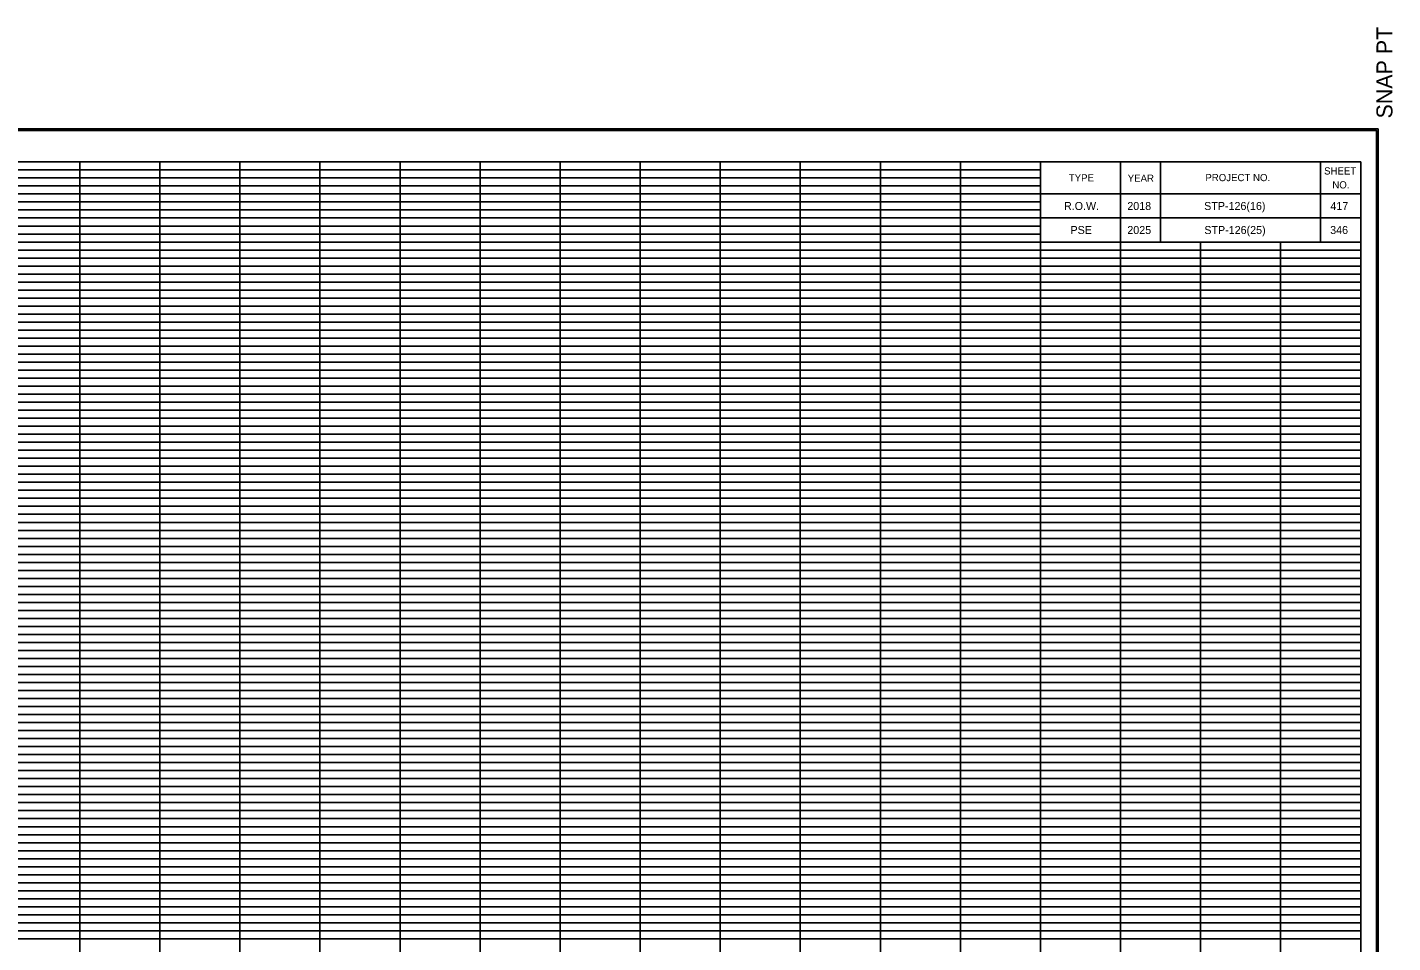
# Model space of a CAD drawing. Extents: x 980 to 2228, y 978 to 2394.
# Drawn here: x 1153.4 to 1324, y 1652.5 to 1766.8 of the extents above; entities that cross this region are included whole.
import ezdxf

# ---------------------------------------------------------------- set-up
doc = ezdxf.new("R2010")
doc.units = 0
for name, color, linetype in [('DESIGN - SCRATCH - User 1', 7, 'Continuous'), ('DESIGN - SHEET - Corner Text', 7, 'Continuous'), ('DESIGN - SHEET - Light Grid', 7, 'Continuous'), ('DESIGN - SHEET - Linework', 7, 'Continuous'), ('DESIGN - SHEET - Plot Shape', 7, 'Continuous'), ('DESIGN - TYPICAL - Finished Grade and Subgrade', 7, 'Continuous')]:
    doc.layers.add(name, color=color, linetype=linetype)

# ---------------------------------------------------------------- blocks, each defined once
blk = doc.blocks.new('XSTSHT')
at = {"layer": 'DESIGN - SCRATCH - User 1'}
for p, q in [((28.5, 20.45), (28.5, 20.45)), ((29.24, 20.45), (29.24, 20.45)), ((30.49, 20.45), (30.49, 20.45)), ((31.74, 20.45), (31.74, 20.45)), ((28.5, 20.15), (28.5, 20.15)), ((29.24, 20.15), (29.24, 20.15)), ((30.49, 20.15), (30.49, 20.15)), ((31.74, 20.15), (31.74, 20.15))]:
    blk.add_line(p, q, dxfattribs=at)
at = {"layer": 'DESIGN - SHEET - Light Grid'}
for p, q in [((8, 20.9), (16, 20.9)), ((16, 20.9), (24, 20.9)), ((24, 20.9), (28, 20.9)), ((8, 20.8), (16, 20.8)), ((8, 20.7), (16, 20.7)), ((16, 20.8), (24, 20.8)), ((16, 20.7), (24, 20.7)), ((24, 20.8), (28, 20.8)), ((24, 20.7), (28, 20.7)), ((8, 20.6), (16, 20.6)), ((8, 20.5), (16, 20.5)), ((16, 20.6), (24, 20.6)), ((16, 20.5), (24, 20.5)), ((24, 20.6), (28, 20.6)), ((24, 20.5), (28, 20.5)), ((8, 20.4), (16, 20.4)), ((8, 20.3), (16, 20.3)), ((16, 20.4), (24, 20.4)), ((16, 20.3), (24, 20.3)), ((24, 20.4), (28, 20.4)), ((24, 20.3), (28, 20.3)), ((8, 20.2), (16, 20.2)), ((16, 20.2), (24, 20.2)), ((24, 20.2), (28, 20.2)), ((8, 20.1), (16, 20.1)), ((16, 20.1), (24, 20.1)), ((24, 20.1), (28, 20.1)), ((8, 19.9), (16, 19.9)), ((8, 19.8), (16, 19.8)), ((16, 19.9), (24, 19.9)), ((16, 19.8), (24, 19.8)), ((24, 19.9), (32, 19.9)), ((24, 19.8), (32, 19.8)), ((8, 19.7), (16, 19.7)), ((16, 19.7), (24, 19.7)), ((24, 19.7), (32, 19.7)), ((8, 19.6), (16, 19.6)), ((8, 19.5), (16, 19.5)), ((16, 19.6), (24, 19.6)), ((16, 19.5), (24, 19.5)), ((24, 19.6), (32, 19.6)), ((24, 19.5), (32, 19.5)), ((8, 19.4), (16, 19.4)), ((8, 19.3), (16, 19.3)), ((16, 19.4), (24, 19.4)), ((16, 19.3), (24, 19.3)), ((24, 19.4), (32, 19.4)), ((24, 19.3), (32, 19.3)), ((8, 19.2), (16, 19.2)), ((16, 19.2), (24, 19.2)), ((24, 19.2), (32, 19.2)), ((8, 19.1), (16, 19.1)), ((16, 19.1), (24, 19.1)), ((24, 19.1), (32, 19.1)), ((8, 18.9), (16, 18.9)), ((8, 18.8), (16, 18.8)), ((16, 18.9), (24, 18.9)), ((16, 18.8), (24, 18.8)), ((24, 18.9), (32, 18.9)), ((24, 18.8), (32, 18.8)), ((8, 18.7), (16, 18.7)), ((8, 18.6), (16, 18.6)), ((16, 18.7), (24, 18.7)), ((16, 18.6), (24, 18.6)), ((24, 18.7), (32, 18.7)), ((24, 18.6), (32, 18.6)), ((8, 18.5), (16, 18.5)), ((16, 18.5), (24, 18.5)), ((24, 18.5), (32, 18.5)), ((8, 18.4), (16, 18.4)), ((8, 18.3), (16, 18.3)), ((16, 18.4), (24, 18.4)), ((16, 18.3), (24, 18.3)), ((24, 18.4), (32, 18.4)), ((24, 18.3), (32, 18.3)), ((8, 18.2), (16, 18.2)), ((8, 18.1), (16, 18.1)), ((16, 18.2), (24, 18.2)), ((16, 18.1), (24, 18.1)), ((24, 18.2), (32, 18.2)), ((24, 18.1), (32, 18.1)), ((8, 17.9), (16, 17.9)), ((8, 17.8), (16, 17.8)), ((16, 17.9), (24, 17.9)), ((16, 17.8), (24, 17.8)), ((24, 17.9), (32, 17.9)), ((24, 17.8), (32, 17.8)), ((8, 17.7), (16, 17.7)), ((8, 17.6), (16, 17.6)), ((16, 17.7), (24, 17.7)), ((16, 17.6), (24, 17.6)), ((24, 17.7), (32, 17.7)), ((24, 17.6), (32, 17.6)), ((8, 17.5), (16, 17.5)), ((8, 17.4), (16, 17.4)), ((16, 17.5), (24, 17.5)), ((16, 17.4), (24, 17.4)), ((24, 17.5), (32, 17.5)), ((24, 17.4), (32, 17.4)), ((8, 17.3), (16, 17.3)), ((16, 17.3), (24, 17.3)), ((24, 17.3), (32, 17.3)), ((8, 17.2), (16, 17.2)), ((8, 17.1), (16, 17.1)), ((16, 17.2), (24, 17.2)), ((16, 17.1), (24, 17.1)), ((24, 17.2), (32, 17.2)), ((24, 17.1), (32, 17.1)), ((8, 16.9), (16, 16.9)), ((16, 16.9), (24, 16.9)), ((24, 16.9), (32, 16.9)), ((8, 16.8), (16, 16.8)), ((16, 16.8), (24, 16.8)), ((24, 16.8), (32, 16.8)), ((8, 16.7), (16, 16.7)), ((8, 16.6), (16, 16.6)), ((16, 16.7), (24, 16.7)), ((16, 16.6), (24, 16.6)), ((24, 16.7), (32, 16.7)), ((24, 16.6), (32, 16.6)), ((8, 16.5), (16, 16.5)), ((8, 16.4), (16, 16.4)), ((16, 16.5), (24, 16.5)), ((16, 16.4), (24, 16.4)), ((24, 16.5), (32, 16.5)), ((24, 16.4), (32, 16.4)), ((8, 16.3), (16, 16.3)), ((16, 16.3), (24, 16.3)), ((24, 16.3), (32, 16.3)), ((8, 16.2), (16, 16.2)), ((8, 16.1), (16, 16.1)), ((16, 16.2), (24, 16.2)), ((16, 16.1), (24, 16.1)), ((24, 16.2), (32, 16.2)), ((24, 16.1), (32, 16.1)), ((8, 15.9), (16, 15.9)), ((16, 15.9), (24, 15.9)), ((24, 15.9), (32, 15.9)), ((8, 15.8), (16, 15.8)), ((8, 15.7), (16, 15.7)), ((16, 15.8), (24, 15.8)), ((16, 15.7), (24, 15.7)), ((24, 15.8), (32, 15.8)), ((24, 15.7), (32, 15.7)), ((8, 15.6), (16, 15.6)), ((16, 15.6), (24, 15.6)), ((24, 15.6), (32, 15.6)), ((8, 15.5), (16, 15.5)), ((8, 15.4), (16, 15.4)), ((16, 15.5), (24, 15.5)), ((16, 15.4), (24, 15.4)), ((24, 15.5), (32, 15.5)), ((24, 15.4), (32, 15.4)), ((8, 15.3), (16, 15.3)), ((8, 15.2), (16, 15.2)), ((16, 15.3), (24, 15.3)), ((16, 15.2), (24, 15.2)), ((24, 15.3), (32, 15.3)), ((24, 15.2), (32, 15.2)), ((8, 15.1), (16, 15.1)), ((16, 15.1), (24, 15.1)), ((24, 15.1), (32, 15.1)), ((8, 14.9), (16, 14.9)), ((16, 14.9), (24, 14.9)), ((24, 14.9), (32, 14.9)), ((8, 14.8), (16, 14.8)), ((8, 14.7), (16, 14.7)), ((16, 14.8), (24, 14.8)), ((16, 14.7), (24, 14.7)), ((24, 14.8), (32, 14.8)), ((24, 14.7), (32, 14.7)), ((8, 14.6), (16, 14.6)), ((8, 14.5), (16, 14.5)), ((16, 14.6), (24, 14.6)), ((16, 14.5), (24, 14.5)), ((24, 14.6), (32, 14.6)), ((24, 14.5), (32, 14.5)), ((8, 14.4), (16, 14.4)), ((16, 14.4), (24, 14.4)), ((24, 14.4), (32, 14.4)), ((8, 14.3), (16, 14.3)), ((8, 14.2), (16, 14.2)), ((16, 14.3), (24, 14.3)), ((16, 14.2), (24, 14.2)), ((24, 14.3), (32, 14.3)), ((24, 14.2), (32, 14.2)), ((8, 14.1), (16, 14.1)), ((16, 14.1), (24, 14.1)), ((24, 14.1), (32, 14.1)), ((8, 13.9), (16, 13.9)), ((16, 13.9), (24, 13.9)), ((24, 13.9), (32, 13.9)), ((8, 13.8), (16, 13.8)), ((8, 13.7), (16, 13.7)), ((16, 13.8), (24, 13.8)), ((16, 13.7), (24, 13.7)), ((24, 13.8), (32, 13.8)), ((24, 13.7), (32, 13.7)), ((8, 13.6), (16, 13.6)), ((8, 13.5), (16, 13.5)), ((16, 13.6), (24, 13.6)), ((16, 13.5), (24, 13.5)), ((24, 13.6), (32, 13.6)), ((24, 13.5), (32, 13.5)), ((8, 13.4), (16, 13.4)), ((16, 13.4), (24, 13.4)), ((24, 13.4), (32, 13.4)), ((8, 13.3), (16, 13.3)), ((8, 13.2), (16, 13.2)), ((16, 13.3), (24, 13.3)), ((16, 13.2), (24, 13.2)), ((24, 13.3), (32, 13.3)), ((24, 13.2), (32, 13.2)), ((8, 13.1), (16, 13.1)), ((16, 13.1), (24, 13.1)), ((24, 13.1), (32, 13.1)), ((8, 12.9), (16, 12.9)), ((8, 12.8), (16, 12.8)), ((16, 12.9), (24, 12.9)), ((16, 12.8), (24, 12.8)), ((24, 12.9), (32, 12.9)), ((24, 12.8), (32, 12.8)), ((8, 12.7), (16, 12.7)), ((16, 12.7), (24, 12.7)), ((24, 12.7), (32, 12.7)), ((8, 12.6), (16, 12.6)), ((8, 12.5), (16, 12.5)), ((16, 12.6), (24, 12.6)), ((16, 12.5), (24, 12.5)), ((24, 12.6), (32, 12.6)), ((24, 12.5), (32, 12.5)), ((8, 12.4), (16, 12.4)), ((8, 12.3), (16, 12.3)), ((16, 12.4), (24, 12.4)), ((16, 12.3), (24, 12.3)), ((24, 12.4), (32, 12.4)), ((24, 12.3), (32, 12.3)), ((8, 12.2), (16, 12.2)), ((16, 12.2), (24, 12.2)), ((24, 12.2), (32, 12.2)), ((8, 12.1), (16, 12.1)), ((16, 12.1), (24, 12.1)), ((24, 12.1), (32, 12.1)), ((8, 11.9), (16, 11.9)), ((8, 11.8), (16, 11.8)), ((16, 11.9), (24, 11.9)), ((16, 11.8), (24, 11.8)), ((24, 11.9), (32, 11.9)), ((24, 11.8), (32, 11.8)), ((8, 11.7), (16, 11.7)), ((8, 11.6), (16, 11.6)), ((16, 11.7), (24, 11.7)), ((16, 11.6), (24, 11.6)), ((24, 11.7), (32, 11.7)), ((24, 11.6), (32, 11.6)), ((8, 11.5), (16, 11.5)), ((16, 11.5), (24, 11.5)), ((24, 11.5), (32, 11.5)), ((8, 11.4), (16, 11.4)), ((8, 11.3), (16, 11.3)), ((16, 11.4), (24, 11.4)), ((16, 11.3), (24, 11.3)), ((24, 11.4), (32, 11.4)), ((24, 11.3), (32, 11.3))]:
    blk.add_line(p, q, dxfattribs=at)
at = {"layer": 'DESIGN - SHEET - Linework'}
for p, q in [((-1.823, 21.414), (32.217, 21.414)), ((32.217, 21.414), (32.217, -0.414)), ((16, 0), (16, 21)), ((17, 0), (17, 21)), ((18, 0), (18, 21)), ((19, 0), (19, 21)), ((20, 0), (20, 21)), ((21, 0), (21, 21)), ((22, 0), (22, 21)), ((23, 0), (23, 21)), ((24, 0), (24, 21)), ((25, 0), (25, 21)), ((26, 0), (26, 21)), ((27, 0), (27, 21)), ((0, 20), (28, 20)), ((28, 0), (28, 20)), ((29, 0), (29, 20)), ((30, 0), (30, 20)), ((31, 0), (31, 20)), ((0, 19), (32, 19)), ((0, 18), (32, 18)), ((0, 17), (32, 17)), ((0, 16), (32, 16)), ((0, 15), (32, 15)), ((0, 14), (32, 14)), ((0, 13), (32, 13)), ((0, 12), (32, 12))]:
    blk.add_line(p, q, dxfattribs=at)
for points in [[(0, 21), (0, 0), (32, 0), (32, 21), (0, 21)], [(28, 21), (28, 20), (32, 20), (32, 21), (31.5, 21), (31.5, 20), (29.5, 20), (29.5, 21), (29, 21), (29, 20), (32, 20), (28, 20), (28, 20.3), (32, 20.3), (32, 20.6), (28, 20.6)]]:
    blk.add_lwpolyline(points, dxfattribs=at)
at = {"layer": 'DESIGN - SHEET - Plot Shape'}
for points in [[(-1.803, 21.394), (32.197, 21.394), (32.197, -0.394), (-1.803, -0.394)], [(-0.85, 21), (32, 21), (32, -0.25), (-0.85, -0.25)]]:
    blk.add_lwpolyline(points, close=True, dxfattribs=at)
at = {"layer": 'DESIGN - SHEET - Corner Text'}
blk.add_text('  SNAP PT', height=0.2, rotation=90, dxfattribs=at).set_placement((32.397, 21.394))
for s, p in [('TYPE', (28.354, 20.756)), ('YEAR', (29.09, 20.752)), ('PROJECT NO.', (30.06, 20.76)), ('SHEET', (31.543, 20.843)), ('NO.', (31.646, 20.669))]:
    blk.add_text(s, height=0.09, dxfattribs=at).set_placement(p)

msp = doc.modelspace()

# ---------------------------------------------------------------- linework, layer by layer
at = {"layer": 'DESIGN - SHEET - Plot Shape'}
msp.add_lwpolyline([(991.5, 1750), (1320, 1750), (1320, 1537.5), (991.5, 1537.5)], close=True, dxfattribs=at)

# ---------------------------------------------------------------- block references
at = {"layer": 'DESIGN - TYPICAL - Finished Grade and Subgrade', "xscale": 10, "yscale": 10}
msp.add_blockref('XSTSHT', (1000, 1540), dxfattribs=at)

# ---------------------------------------------------------------- texts
at = {"layer": 'DESIGN - SHEET - Corner Text'}
for s, p in [('R.O.W.', (1282.94, 1744)), ('2018', (1290.85, 1744)), ('STP-126(16)', (1300.45, 1744)), ('417', (1316.22, 1744)), ('PSE', (1283.75, 1741)), ('2025', (1290.85, 1741)), ('STP-126(25)', (1300.47, 1741)), ('346', (1316.19, 1741))]:
    msp.add_text(s, height=1, dxfattribs=at).set_placement(p)

doc.saveas('drawing.dxf')
